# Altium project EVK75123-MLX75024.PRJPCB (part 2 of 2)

## Sheet Interfaces.SchDoc: Interfaces / PLL / Temp. Sensors
size A3; CheckedBy: ROB; Author: Vorname Nachname; DrawnBy: DST; Organization: BECOM BLUETECHNIX; Address1: Gutheil-Schoder-Gasse 17; Address2: A - 1230 Wien; Address3: AUSTRIA; DocumentNumber: 2; Revision: V1.0; SheetNumber: 2; SheetTotal: 4
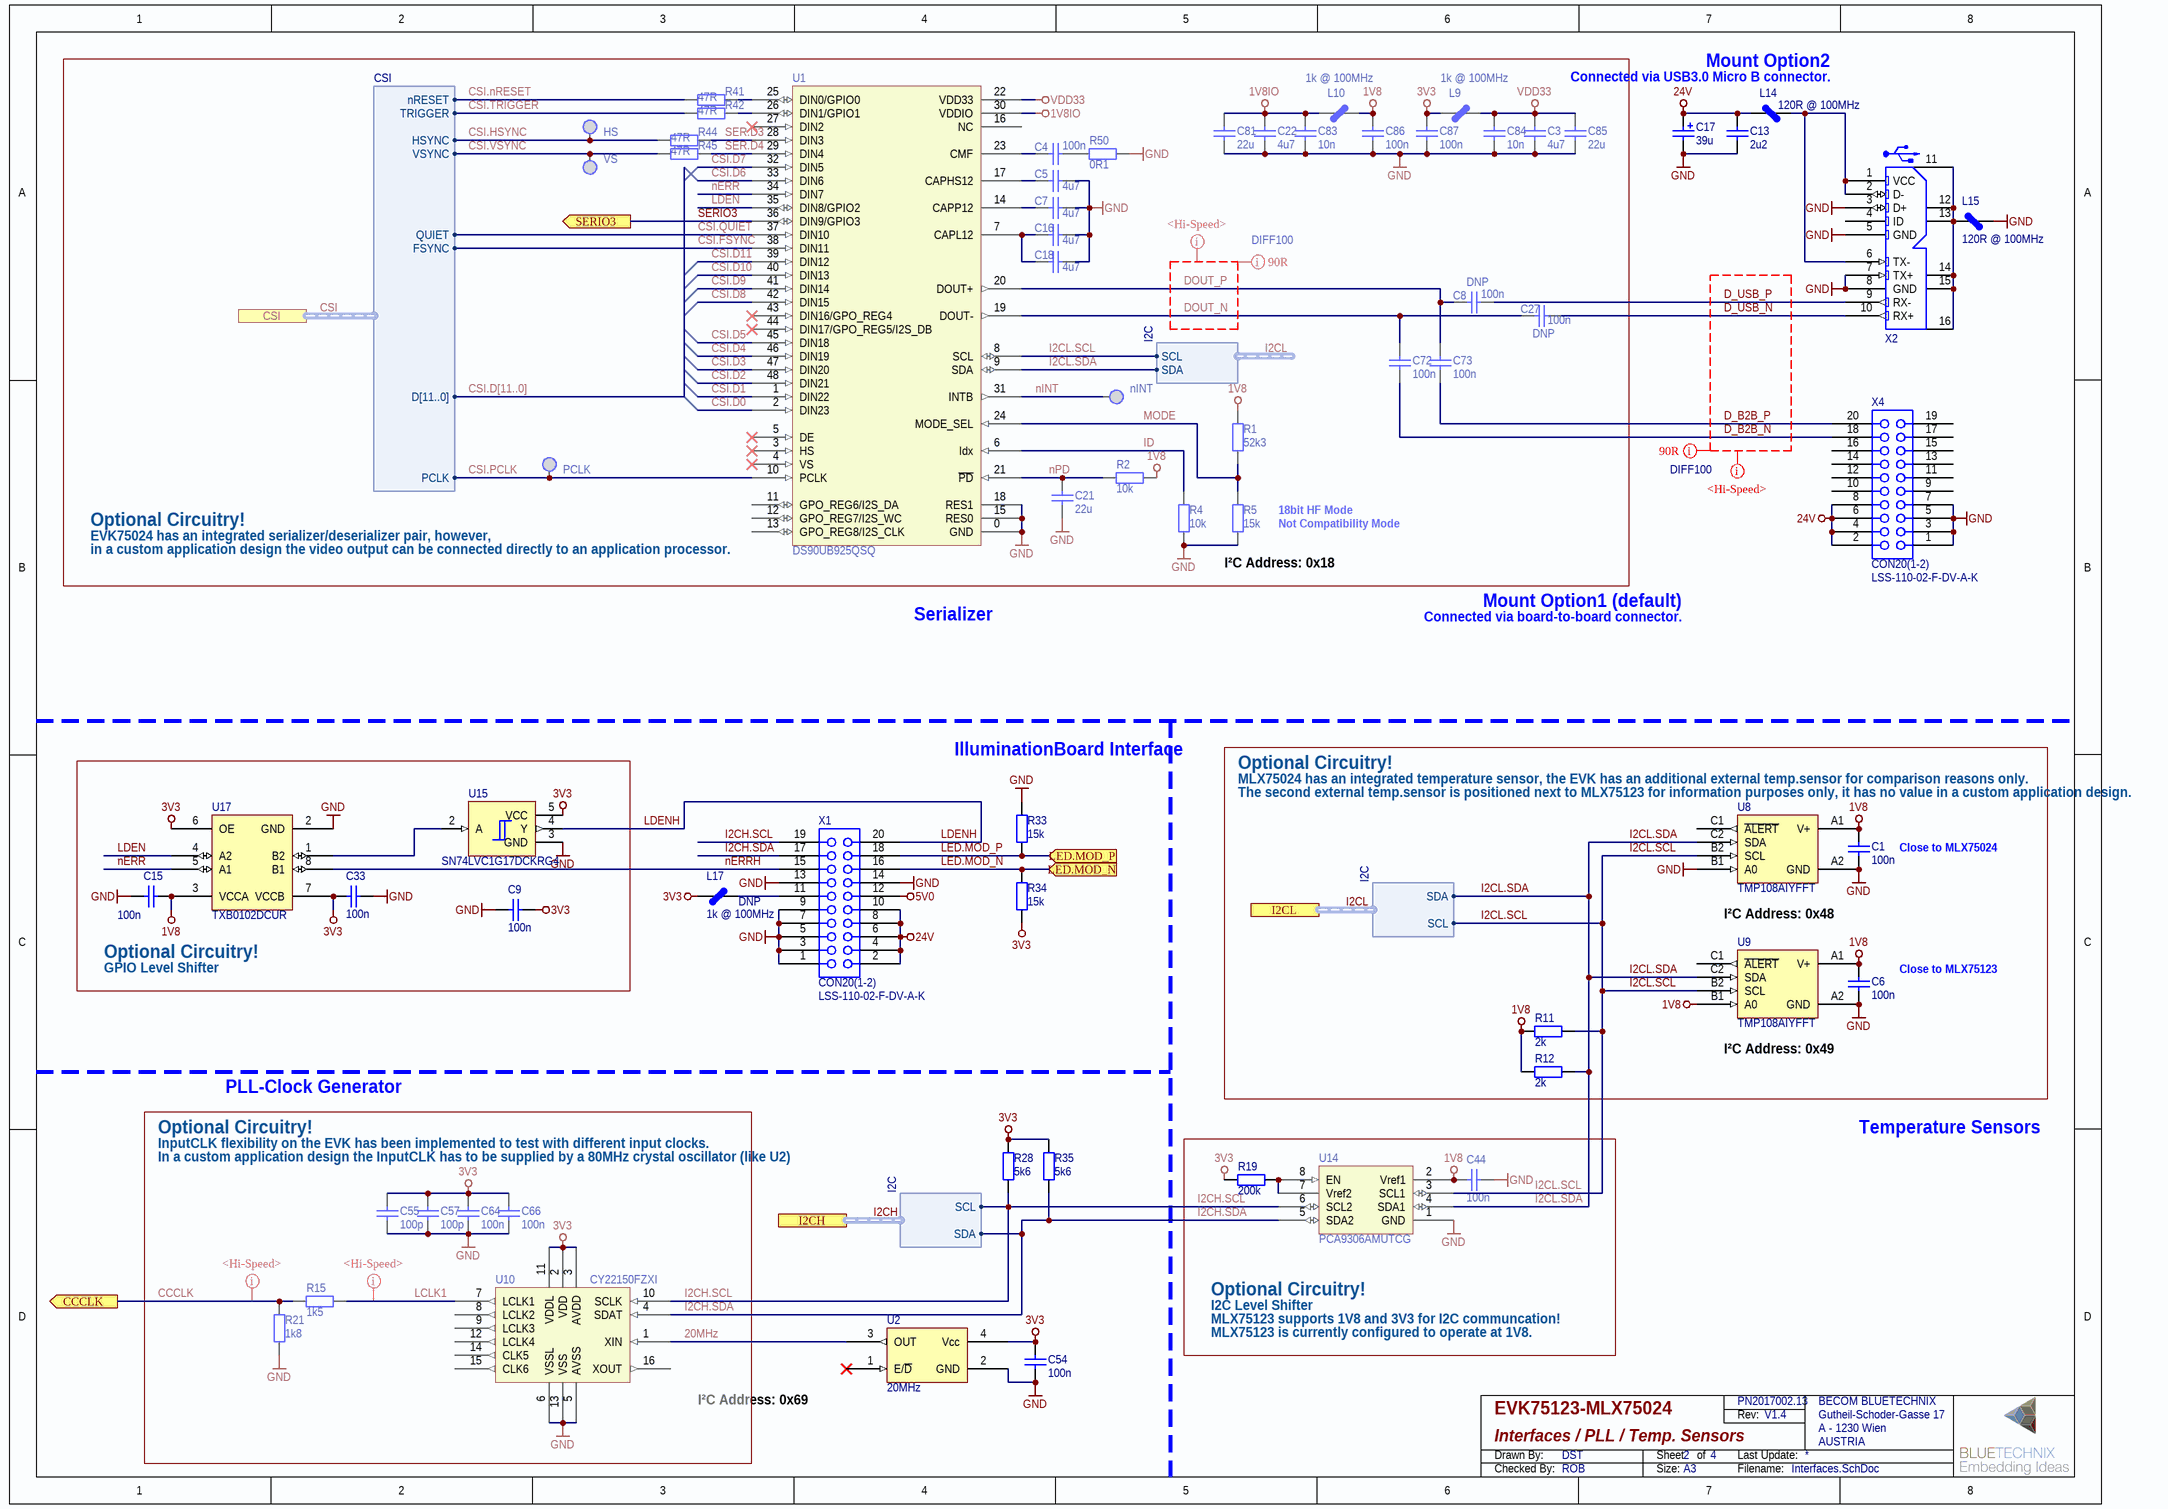
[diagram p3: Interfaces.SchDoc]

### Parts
C1  C: 100n  [0402]  (hidden comment: Capacitor non-polarized)
C3  C: 4u7  [0603]  (hidden comment: Capacitor non-polarized)
C4  C: 100n  [0402]  (hidden comment: Capacitor non-polarized)
C5  C: 4u7  [0603]  (hidden comment: Capacitor non-polarized)
C6  C: 100n  [0402]  (hidden comment: Capacitor non-polarized)
C7  C: 4u7  [0603]  (hidden comment: Capacitor non-polarized)
C8  C: 100n  MountOption: DNP  [0805]  (hidden comment: Capacitor non-polarized)
C9  C: 100n  [0402]  (hidden comment: Capacitor non-polarized)
C13  C: 2u2  [1210]  (hidden comment: Capacitor non-polarized)
C15  C: 100n  [0402]  (hidden comment: Capacitor non-polarized)
C16  C: 4u7  [0603]  (hidden comment: Capacitor non-polarized)
C17  C: 39u  [ELKO_SMD-8x7]  (hidden comment: Polarized Capicator)
C18  C: 4u7  [0603]  (hidden comment: Capacitor non-polarized)
C21  C: 22u  [0805]  (hidden comment: Capacitor non-polarized)
C22  C: 4u7  [0603]  (hidden comment: Capacitor non-polarized)
C27  C: 100n  MountOption: DNP  [0805]  (hidden comment: Capacitor non-polarized)
C33  C: 100n  [0402]  (hidden comment: Capacitor non-polarized)
C44  C: 100n  [0402]  (hidden comment: Capacitor non-polarized)
C54  C: 100n  [0402]  (hidden comment: Capacitor non-polarized)
C55  C: 100p  [0402]  (hidden comment: Capacitor non-polarized)
C57  C: 100p  [0402]  (hidden comment: Capacitor non-polarized)
C64  C: 100n  [0402]  (hidden comment: Capacitor non-polarized)
C66  C: 100n  [0402]  (hidden comment: Capacitor non-polarized)
C72  C: 100n  [0805]  (hidden comment: Capacitor non-polarized)
C73  C: 100n  [0805]  (hidden comment: Capacitor non-polarized)
C81  C: 22u  [0805]  (hidden comment: Capacitor non-polarized)
C83  C: 10n  [0603]  (hidden comment: Capacitor non-polarized)
C84  C: 10n  [0603]  (hidden comment: Capacitor non-polarized)
C85  C: 22u  [0805]  (hidden comment: Capacitor non-polarized)
C86  C: 100n  [0402]  (hidden comment: Capacitor non-polarized)
C87  C: 100n  [0402]  (hidden comment: Capacitor non-polarized)
HS  Test Pad  [PAD_1mm_SMD]  (value not drawn)  (no BOM)
L9  Z: 1k @ 100MHz  [0603]  (hidden comment: Ferrite)
L10  Z: 1k @ 100MHz  [0603]  (hidden comment: Ferrite)
L14  Z: 120R @ 100MHz  [0805]  (hidden comment: Ferrite)
L15  Z: 120R @ 100MHz  [0805]  (hidden comment: Ferrite)
L17  Z: 1k @ 100MHz  MountOption: DNP  [0603]  (hidden comment: Ferrite)
nINT  Test Pad  [PAD_1mm_SMD]  (value not drawn)  (no BOM)
PCLK  Test Pad  [PAD_1mm_SMD]  (value not drawn)  (no BOM)
R1  R: 52k3  [0402]  (hidden comment: Resistor)
R2  R: 10k  [0402]  (hidden comment: Resistor)
R4  R: 10k  [0402]  (hidden comment: Resistor)
R5  R: 15k  [0402]  (hidden comment: Resistor)
R11  R: 2k  [0402]  (hidden comment: Resistor)
R12  R: 2k  [0402]  (hidden comment: Resistor)
R15  R: 1k5  [0402]  (hidden comment: Resistor)
R19  R: 200k  [0402]  (hidden comment: Resistor)
R21  R: 1k8  [0402]  (hidden comment: Resistor)
R28  R: 5k6  [0402]  (hidden comment: Resistor)
R33  R: 15k  [0402]  (hidden comment: Resistor)
R34  R: 15k  [0402]  (hidden comment: Resistor)
R35  R: 5k6  [0402]  (hidden comment: Resistor)
R41  R: 47R  [0402]  (hidden comment: Resistor)
R42  R: 47R  [0402]  (hidden comment: Resistor)
R44  R: 47R  [0402]  (hidden comment: Resistor)
R45  R: 47R  [0402]  (hidden comment: Resistor)
R50  R: 0R1  [0402]  (hidden comment: Resistor)
U1  NAME: DS90UB925QSQ  [QFN48-0.5-7-largeEP]  (hidden comment: DS90UB925)
U2  Frequenz: 20MHz  [JO32]  (hidden comment: XTAL-IC)
U8  NAME: TMP108AIYFFT  [BGA6-0.4-0.25-1.2x0.8]  (hidden comment: TMP108)
U9  NAME: TMP108AIYFFT  [BGA6-0.4-0.25-1.2x0.8]  (hidden comment: TMP108)
U10  NAME: CY22150FZXI  [TSSOP16-0.65--6.4]  (hidden comment: PSoC Mixed Signal-Array)
U14  NAME: PCA9306AMUTCG  [VQFN8-0.5-1.6-0.6]  (hidden comment: PCA9306)
U15  NAME: SN74LVC1G17DCKRG4  [SOT353-0.65--2.6]  (hidden comment: SN74LVC1G17)
U17  NAME: TXB0102DCUR  [VSSOP8-0.5--3.2]  (hidden comment: TXB0102)
VS  Test Pad  [PAD_1mm_SMD]  (value not drawn)  (no BOM)
X1  CON20(1-2)  NAME: LSS-110-02-F-DV-A-K  [SAM-LSS-110-02-F-DV-A]
X2  USB_micro_3  [USB_micro_3]  (value not drawn)
X4  CON20(1-2)  NAME: LSS-110-02-F-DV-A-K  [SAM-LSS-110-02-F-DV-A]

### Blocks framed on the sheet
Optional Circuitry!: C3-C5 C7 C8 C16 C18 C21 C22 C27 C72 C73 C81 C83-C87 HS L9 L10 nINT PCLK R1 R2 R4 R5 R41 R42 R44 R45 R50 U1 VS
Optional Circuitry!: C9 C15 C33 U15 U17
Optional Circuitry!: C1 C6 R11 R12 U8 U9
Optional Circuitry!: C44 R19 U14

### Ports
CCCLK (out), CSI (harness CSI), I2CH (harness I2C), I2CL (harness I2C), LED.MOD_N (in), LED.MOD_P (in), SERIO3 (out)

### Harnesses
CSI: D[11..0], VSYNC, HSYNC, PCLK, QUIET, FSYNC, TRIGGER, nRESET
I2C: SCL, SDA

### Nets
1V8: C1.2 C6.2 C15.1 C44.2 C86.1 L10.2 R1.2 R2.2 R11.1 R12.1 U8.A1(V+) U9.A1(V+) U9.B1(A0) U14.2(Vref1) U17.3(VCCA)
1V8IO: C22.1 C81.2 C83.2 L10.1 U1.30(VDDIO)
3V3: C9.1 C33.2 C54.1 C55.2 C57.2 C64.2 C66.2 C87.1 L9.1 L17.1 R19.1 R28.2 R34.2 R35.2 U2.4(Vcc) U10.2(VDD) U10.3(AVDD) U10.11(VDDL) U15.5(VCC) U17.6(OE) U17.7(VCCB)
5V0: X1.12
24V: C13.2 C17.1 L14.1 X1.2 X1.4 X1.6 X1.8 X1.10 X4.2 X4.4 X4.6 X4.8
GND: C1.1 C3.2 C5.1 C6.1 C7.1 C9.2 C13.1 C15.2 C16.1 C17.2 C18.1 C21.1 C22.2 C33.1 C44.1 C54.2 C55.1 C57.1 C64.1 C66.1 C81.1 C83.1 C84.1 C85.1 C86.2 C87.2 L15.2 R4.1 R5.1 R21.1 R33.1 R50.1 U1.0(GND) U1.15(RES0) U1.18(RES1) U2.2(GND) U8.A2(GND) U8.B1(A0) U9.A2(GND) U10.5(AVSS) U10.6(VSSL) U10.13(VSS) U14.1(GND) U15.3(GND) U17.2(GND) X1.1 X1.3 X1.5 X1.7 X1.9 X1.13 X1.14 X2.3(D+) X2.5(GND) X2.7(TX+) X2.8(GND) X4.1 X4.3 X4.5 X4.7
VDD33: C3.1 C84.2 C85.2 L9.2 U1.22(VDD33)
20MHz: U2.3(OUT) U10.1(XIN)
CCCLK: R15.1 R21.2 ; port CCCLK
CSI.D0: U1.2(DIN23)
CSI.D1: U1.1(DIN22)
CSI.D2: U1.48(DIN21)
CSI.D3: U1.47(DIN20)
CSI.D4: U1.46(DIN19)
CSI.D5: U1.45(DIN18)
CSI.D6: U1.33(DIN6)
CSI.D7: U1.32(DIN5)
CSI.D8: U1.42(DIN15)
CSI.D9: U1.41(DIN14)
CSI.D10: U1.40(DIN13)
CSI.D11: U1.39(DIN12)
CSI.FSYNC: U1.38(DIN11) ; port CSI.FSYNC
CSI.HSYNC: HS.1 R44.1 ; port CSI.HSYNC
CSI.nRESET: R41.1 ; port CSI.nRESET
CSI.PCLK: PCLK.1 U1.10(PCLK) ; port CSI.PCLK
CSI.QUIET: U1.37(DIN10) ; port CSI.QUIET
CSI.TRIGGER: R42.1 ; port CSI.TRIGGER
CSI.VSYNC: R45.1 VS.1 ; port CSI.VSYNC
D_B2B_N: C72.1 X4.18
D_B2B_P: C73.1 X4.20
D_USB_N: C27.2 X2.10(RX+)
D_USB_P: C8.2 X2.9(RX-)
DOUT_N: C27.1 C72.2 U1.19(DOUT-)
DOUT_P: C8.1 C73.2 U1.20(DOUT+)
I2CH.SCL: R28.1 U10.10(SCLK) U14.6(SCL2) X1.19 ; port I2CH.SCL
I2CH.SDA: R35.1 U10.4(SDAT) U14.5(SDA2) X1.17 ; port I2CH.SDA
I2CL.SCL: R11.2 U1.8(SCL) U8.B2(SCL) U9.B2(SCL) U14.3(SCL1) ; port I2CL.SCL
I2CL.SDA: R12.2 U1.9(SDA) U8.C2(SDA) U9.C2(SDA) U14.4(SDA1) ; port I2CL.SDA
ID: R4.2 U1.6(Idx)
LCLK1: R15.2 U10.7(LCLK1)
LDEN: U1.35(DIN8/GPIO2) U17.4(A2)
LDENH: U15.4(Y) X1.20
LED.MOD_N: R34.1 X1.16 ; port LED.MOD_N
LED.MOD_P: R33.2 X1.18 ; port LED.MOD_P
MODE: R1.1 R5.2 U1.24(MODE_SEL)
nERR: U1.34(DIN7) U17.5(A1)
nERRH: U17.8(B1) X1.15
nINT: nINT.1 U1.31(INTB)
nPD: C21.2 R2.1 U1.21(~{PD})
SER.D3: R44.2 U1.28(DIN3)
SER.D4: R45.2 U1.29(DIN4)
SERIO3: U1.36(DIN9/GPIO3) ; port SERIO3
NetC4_1: C4.1 R50.2
NetC4_2: C4.2 U1.23(CMF)
NetC5_2: C5.2 U1.17(CAPHS12)
NetC7_2: C7.2 U1.14(CAPP12)
NetC16_2: C16.2 C18.2 U1.7(CAPL12)
NetL14_2: L14.2 X2.1(VCC) X2.2(D-) X2.6(TX-)
NetL15_1: L15.1 X2.11 X2.12 X2.13 X2.14 X2.15 X2.16
NetL17_2: L17.2 X1.11
NetR19_2: R19.2 U14.7(Vref2) U14.8(EN)
NetR41_2: R41.2 U1.25(DIN0/GPIO0)
NetR42_2: R42.2 U1.26(DIN1/GPIO1)
NetU15_2: U15.2(A) U17.1(B2)

Not connected (* = marked no-connect by the designer): U1 3(HS)* 4(VS)* 5(DE)* 11(GPO_REG6/I2S_DA) 12(GPO_REG7/I2S_WC) 13(GPO_REG8/I2S_CLK) 16(NC) 27(DIN2)* 43(DIN16/GPO_REG4)* 44(DIN17/GPO_REG5/I2S_DB)*; U2 1(E/~{D})*; U8 C1(~{ALERT}); U9 C1(~{ALERT}); U10 8(LCLK2) 9(LCLK3) 12(LCLK4) 14(CLK5) 15(CLK6) 16(XOUT); X2 4(ID); X4 9 10 11 12 13 14 15 16 17 19

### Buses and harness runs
bus CSI.D[11..0]
harness CSI = port CSI
harness I2CH = port I2CH
harness I2CL = port I2CL

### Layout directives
net class <Hi-Speed>: CCCLK, D_B2B_N, D_B2B_P, D_USB_N, D_USB_P, DOUT_N, DOUT_P, LCLK1
differential pair; net class DIFF100: D_B2B_N, D_B2B_P, D_USB_N, D_USB_P, DOUT_N, DOUT_P

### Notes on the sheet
- Mount Option2
- Connected via USB3.0 Micro B connector.
- (near R5) 18bit HF Mode
- EVK75024 has an integrated serializer/deserializer pair, however,
- (near U1) in a custom application design the video output can be connected directly to an application processor.
- (near R5) I²C Address: 0x18
- (near R5) Not Compatibility Mode
- Serializer
- Connected via board-to-board connector.
- (near X4) Mount Option1 (default)
- IlluminationBoard Interface
- MLX75024 has an integrated temperature sensor, the EVK has an additional external temp.sensor for comparison reasons only.
- The second external temp.sensor is positioned next to MLX75123 for information purposes only, it has no value in a custom application design.
- (near C1) Close to MLX75024
- I²C Address: 0x48
- GPIO Level Shifter
- (near C6) Close to MLX75123
- I²C Address: 0x49
- PLL-Clock Generator
- Optional Circuitry!
- In a custom application design the InputCLK has to be supplied by a 80MHz crystal oscillator (like U2)
- InputCLK flexibility on the EVK has been implemented to test with different input clocks.
- Temperature Sensors
- I2C Level Shifter
- MLX75123 supports 1V8 and 3V3 for I2C communcation!
- MLX75123 is currently configured to operate at 1V8.
- (near U10) I²C Address: 0x69

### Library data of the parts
C1 C4 C6 C15 C33 C44 C64 C66 C86 C87 = 54C877D5-E705-4C14-AD3D-8F4F7B57D597: C-0402-100n-16V-10%; Manufacturer: Murata; ArticleNumber: 710-0138; NAME: GRM155R71C104KA88D; Inventory Storage Name: LBaut; Inventory Storage Section: C3; Sachgruppe: C_KERAMIK; SachgruppeCode: Keramikscheiben; IsReviewed: 1; U: 16V; Toleranz: 10%; Dielektrikum: X7R; T_Koeffizient: ± 15%; T-bereich: -55°C : +125°C; Montage: SMD; InternalPrice: 0,009756; InternalStock: 539102
C3 C5 C7 C16 C18 C22 = E75EC942-B97D-4F35-9B30-0E69ABA45798: C-0603-4u7-6.3V-10%; Manufacturer: Kemet; ArticleNumber: 710-0008; NAME: C0603C475K9PAC; Inventory Storage Name: LBaut; Inventory Storage Section: CR1; Sachgruppe: C_KERAMIK; SachgruppeCode: Keramikscheiben; IsReviewed: 1; InternalPrice: 0,00975; InternalStock: 19132; U: 6.3V; Toleranz: 10%; Dielektrikum: X5R; T_Koeffizient: ± 15%; T-bereich: -55°C : +85°C; Montage: SMD
C8 C27 C72 C73 = 673ACA82-F2DF-4178-940F-1238A813E141: C-0805-100n-50V-10%; Manufacturer: AVX; ArticleNumber: 710-0012; NAME: 08055C104KAZ2A; Inventory Storage Name: LBaut; Inventory Storage Section: C1; Sachgruppe: C_KERAMIK; SachgruppeCode: Keramikscheiben; IsReviewed: 1; InternalPrice: 0,053478; InternalStock: 242; U: 50V; Toleranz: 10%; Dielektrikum: X7R; T_Koeffizient: ± 30ppm/°C; T-bereich: -55°C : +125°C; Montage: SMD
C9 C54 = 54C877D5-E705-4C14-AD3D-8F4F7B57D597: C-0402-100n-16V-10%; Manufacturer: Murata; ArticleNumber: 710-0138; NAME: GRM155R71C104KA88D; Inventory Storage Name: LBaut; Inventory Storage Section: C3; Sachgruppe: C_KERAMIK; SachgruppeCode: Keramikscheiben; IsReviewed: 1; Dielektrikum: X7R; Montage: SMD; T-bereich: -55°C : +125°C; T_Koeffizient: ± 15%; Toleranz: 10%; U: 16V; InternalPrice: 0,009756; InternalStock: 539102
C13 = c11633e3-883f-4ea1-bab5-305a930c1712: C-1210-2u2-100V-X7R; Manufacturer: Kemet; ArticleNumber: 710-0311; NAME: C1210C225K1RACTU; Inventory Storage Name: LBaut; Inventory Storage Section: C6; Sachgruppe: C_KERAMIK; SachgruppeCode: Keramikscheiben; IsReviewed: 1; InternalPrice: 0,222241; InternalStock: 196; U: 100V; Toleranz: 10%; Dielektrikum: X7R; T_Koeffizient: ± 15%; T-bereich: -55°C : +125°C; Montage: SMD
C17 = 44276342-0de9-47a7-a7a6-11334c4a2d95: C-39u-35V-20%-30mR; Manufacturer: Panasonic; ArticleNumber: 710-0385; NAME: 35SVPF39M; Inventory Storage Name: LBaut; Sachgruppe: C_ALUMINIUM_ELKO; SachgruppeCode: Aluminium Elektrolyt; IsReviewed: 1; U: 35V; Toleranz: 20%; ESR: 30mR; Z: 30mR @ 100kHz; T-bereich: -55°C : +105°C; Lebensdauer: 5000h @ 105°C; Bauform: 8.3x8.3x6.9; Montage: SMD; Kommentar: Irip=2.8A; InternalPrice: 0,442083; InternalStock: 68; Inventory Storage Section: C7
C21 C81 C85 = 9F754684-D939-469A-B40A-D1B375B83304: C-0805-22u-6.3V-20%; Manufacturer: AVX; ArticleNumber: 710-0282; NAME: 08056D226MAT2A; Inventory Storage Name: LBaut; Inventory Storage Section: C6; Sachgruppe: C_KERAMIK; SachgruppeCode: Keramikscheiben; IsReviewed: 1; InternalPrice: 0,139296; InternalStock: 574; U: 6.3V; Toleranz: 20%; Dielektrikum: X5R; T_Koeffizient: ±15%; T-bereich: -55°C :+125°C; Montage: SMD
C55 C57 = ec10d741-eb09-41f2-b621-026af504b23c: C-0402-100p-50V-5%; Manufacturer: Samsung; ArticleNumber: 710-0302; NAME: CL05C101JB5NNNC; Inventory Storage Name: LBaut; Sachgruppe: C_KERAMIK; SachgruppeCode: Keramikscheiben; IsReviewed: 1; InternalPrice: 0,006666; InternalStock: 8674; U: 50V; Toleranz: 5%; Dielektrikum: C0G; T-bereich: -55°C : +125°C; Montage: SMD; Inventory Storage Section: C6
C83 C84 = 7C0C21CA-74A8-454E-BED5-E74A03E0EDB6: C-0603-10n-25V-5%; Manufacturer: Kemet; ArticleNumber: 710-0271; NAME: C0603C103J3GACTU; Inventory Storage Name: LBaut; Inventory Storage Section: C6; Sachgruppe: C_KERAMIK; SachgruppeCode: Keramikscheiben; IsReviewed: 1; InternalPrice: 0,174117; InternalStock: 264; U: 25V; Toleranz: 5%; Dielektrikum: C0G; T_Koeffizient: ± 30ppm/°C; T-bereich: -55°C : +125°C; Montage: SMD
HS nINT PCLK VS = D58E77CC-74E0-4972-9B60-0D1F1EE06ED8: Test Pad 1mm; Manufacturer: Bluetechnix; ArticleNumber: 810-0021; Inventory Storage Name: L2; Sachgruppe: SV_TEST; IsReviewed: 1; Montage: THD
L9 L10 = EB1B1D42-458D-46E7-BD46-C9CB50225E79: F-0603-1000Z-500mA; Manufacturer: Taiyo Yuden; ArticleNumber: 770-0092; NAME: FBMH1608HM102-T; Inventory Storage Name: LBaut; Inventory Storage Section: I7; Sachgruppe: FI_FERRITPERLEN; SachgruppeCode: Ferritperlen; IsReviewed: 1; InternalPrice: 0,108507; InternalStock: 382; R_dc: 0R45; Frequenz: 900MHz; I_max: 0.5A; Montage: SMD; T-bereich: -40°C : +125°C
L14 L15 = 4558f3ef-a2ca-4732-a97e-33e36c5aad12: F-0805-120Z-5A; Manufacturer: MEC MARCOM; ArticleNumber: 740-0008; NAME: MFB-201209-0120PU; Inventory Storage Name: LBaut; Inventory Storage Section: L2; Sachgruppe: FI_FERRITPERLEN; SachgruppeCode: Ferritperlen; IsReviewed: 1; InternalPrice: 0,063082; InternalStock: 208; R_dc: 0R02; Bandbreite: 110R @ 1GHz; Frequenz: 300MHz; I_max: 5A; Montage: SMD; T-bereich: -55°C : +125°C
L17 = b9289626-3563-4556-94c6-b2bf7f242055: F-0603-1000Z-100mA; Manufacturer: Murata; ArticleNumber: 740-0011; NAME: BLM18BD102SN1D; Inventory Storage Name: LBaut; Inventory Storage Section: L2; Sachgruppe: FI_FERRITPERLEN; SachgruppeCode: Ferritperlen; IsReviewed: 1; InternalPrice: 0,018958; InternalStock: 710; R_dc: 0R85; Frequenz: 200MHz; I_max: 100mA; Montage: SMD; T-bereich: -55°C : +125°C
R1 = 07979F3D-4677-465C-93AF-4C0DB5A9740C: R-0402-52k3-1%; Manufacturer: Multicomp; ArticleNumber: 780-0113; NAME: MC 0.0625W 0402 1% 52K3; Inventory Storage Name: LBaut; Inventory Storage Section: R3; Sachgruppe: R_DICKSCHICHT; SachgruppeCode: Dickschicht; IsReviewed: 1; InternalPrice: 0,022692; InternalStock: 1828; P: 0.0625W; Toleranz: 1%; T_Koeffizient: ± 100ppm/°C; Montage: SMD; T-bereich: -55°C : +155°C
R2 R4 = BCCEBF77-39D2-4523-BB97-913D11062098: R-0402-10k-1%; manufacturer: YAGEO; ArticleNumber: 780-0217; Inventory Storage Name: LBaut; Inventory Storage Section: R5; NAME: RC0402FR-0710KL; Sachgruppe: R_DICKSCHICHT; SachgruppeCode: Dickschicht; Montage: SMD; P: 0.063W; T_Koeffizient: ± 250ppm/°C; Toleranz: 1%; IsReviewed: 1; T-bereich: -55°C : +155°C; InternalPrice: 0,028158; InternalStock: 1616
R5 = 5AE00D73-A272-4484-A2BE-57AC9ABCA7A7: R-0402-15k-1%; Manufacturer: YAGEO; ArticleNumber: 780-0130; NAME: RC0402FR-0715K0L; Inventory Storage Name: LBaut; Inventory Storage Section: R3; Sachgruppe: R_DICKSCHICHT; SachgruppeCode: Dickschicht; IsReviewed: 1; P: 0.063W; Toleranz: 1%; T_Koeffizient: ± 250ppm/°C; Montage: SMD; T-bereich: -55°C : +155°C; InternalPrice: 0,036444; InternalStock: 788
R11 R12 = BC2B87D0-B6C1-44F9-904C-ACAF31BEC71E: R-0402-2k-1%; Manufacturer: MULTICOMP; ArticleNumber: 780-0436; NAME: MC 0.0625W 0402 1% 2K; Inventory Storage Name: LBaut; Inventory Storage Section: R9; Sachgruppe: R_DICKSCHICHT; SachgruppeCode: Dickschicht; IsReviewed: 1; InternalPrice: 0,035294; InternalStock: 30; P: 0.063W; Toleranz: 1%; T_Koeffizient: ± 100ppm/°C; Montage: SMD; T-bereich: -55°C : +155°C
R15 = 9730678D-3891-499B-9B01-A89CC85559C4: R-0402-1k5-1%; Manufacturer: YAGEO; ArticleNumber: 780-0257; NAME: RC0402FR-071K5L; Inventory Storage Name: LBaut; Inventory Storage Section: R6; Sachgruppe: R_DICKSCHICHT; SachgruppeCode: Dickschicht; IsReviewed: 1; InternalPrice: 0,035634; InternalStock: 490; P: 0.063W; Toleranz: 1%; T_Koeffizient: ± 250ppm/°C; Montage: SMD; T-bereich: -55°C : +155°C
R19 = EB4C6C81-BAA5-401A-97FC-7C0F95811618: R-0402-200k-1%; Manufacturer: YAGEO; ArticleNumber: 780-0184; NAME: RC0402FR-07200KL; Inventory Storage Name: LBaut; Inventory Storage Section: R4; Sachgruppe: R_DICKSCHICHT; SachgruppeCode: Dickschicht; IsReviewed: 1; InternalPrice: 0,009047; InternalStock: 1480; P: 0.063W; Toleranz: 1%; T_Koeffizient: ± 100ppm/°C; Montage: SMD; T-bereich: -55°C : +155°C
R21 = 1021EC43-D7C6-4E9F-B4E5-559CA0DA3C67: R-0402-1k8-1%; Manufacturer: YAGEO; ArticleNumber: 780-0124; NAME: RC0402FR-071K8L; Inventory Storage Name: LBaut; Inventory Storage Section: R3; Sachgruppe: R_DICKSCHICHT; SachgruppeCode: Dickschicht; IsReviewed: 1; InternalPrice: 0,005937; InternalStock: 402; P: 0.063W; Toleranz: 1%; T_Koeffizient: ± 250ppm/°C; Montage: SMD
R28 R35 = 83EC2591-E07F-42F5-A99F-8FBBFCE4BDFC: R-0402-5k6-5%; Manufacturer: YAGEO; ArticleNumber: 780-0215; NAME: RC0402JR-075K6L; Inventory Storage Name: LBaut; Inventory Storage Section: R5; Sachgruppe: R_DICKSCHICHT; SachgruppeCode: Dickschicht; IsReviewed: 1; InternalPrice: 0,00795; InternalStock: 952; P: 0.063W; Toleranz: 5%; T_Koeffizient: ± 200ppm/°C; Montage: SMD; T-bereich: -55°C : +150°C
R33 R34 = 5AE00D73-A272-4484-A2BE-57AC9ABCA7A7: R-0402-15k-1%; Manufacturer: YAGEO; ArticleNumber: 780-0130; NAME: RC0402FR-0715K0L; Inventory Storage Name: LBaut; Inventory Storage Section: R3; Sachgruppe: R_DICKSCHICHT; SachgruppeCode: Dickschicht; IsReviewed: 1; InternalPrice: 0,036444; InternalStock: 788; P: 0.063W; Toleranz: 1%; T_Koeffizient: ± 250ppm/°C; Montage: SMD; T-bereich: -55°C : +155°C
R41 R42 R44 R45 = B17B00F1-DBD0-472B-A8A9-768E0D7D14BD: R-0402-47R-5%; Manufacturer: YAEGO; ArticleNumber: 780-0173; NAME: RC0402JR-0747RL; Inventory Storage Name: LBaut; Inventory Storage Section: R4; Sachgruppe: R_DICKSCHICHT; SachgruppeCode: Dickschicht; IsReviewed: 1; P: 0.063W; Toleranz: 5%; T_Koeffizient: ± 200ppm/°C; Montage: SMD; T-bereich: -55°C : +155°C; InternalPrice: 0,023346; InternalStock: 978
R50 = 366df4e7-ff92-4215-b9a2-968f2cab22c9: R-0402-0R1-1%; Manufacturer: PhyComp; ArticleNumber: 780-0603; NAME: RL0402FR-070R1L; Inventory Storage Name: LBaut; Sachgruppe: R_DICKSCHICHT; SachgruppeCode: Dickschicht; IsReviewed: 1; P: 0.063W; Toleranz: 1%; T_Koeffizient: ± 100ppm/°C; Montage: SMD; InternalPrice: 0,0875; InternalStock: 188; Inventory Storage Section: R11
U1 = 1691325b-6bd3-4e9e-84e0-1aaa7d8a455c: DS90UB925Q-Q1 5 to 85 MHz 24-Bit Color FPD-Link III Serializer; Manufacturer: TI; ArticleNumber: 700-1102; Inventory Storage Name: LBaut; Sachgruppe: IC_TREIBER_INTERFACE; SachgruppeCode: Treiber & Interface; IsReviewed: 1; Typ: 24 Bit LVDS Deserializer; Wege: 18/24 : 2; Interface: LVDS; T-bereich: -40°C : +105°C; Bauform: QFN48; Montage: SMD; U: VDD 1.8V, VIO 1.8V : 3.3V; InternalPrice: 8,505555; InternalStock: 10; Inventory Storage Section: U48
U2 = 00cff2d6-5d29-4f0c-95fc-66dce918587e: OSC-JO32-20MHz; Manufacturer: Microchip; ArticleNumber: 760-0134; NAME: DSC1001CL1-020.0000; Inventory Storage Name: LBaut; Sachgruppe: QO_OSZILLATOR; SachgruppeCode: Oszillatoren; IsReviewed: 1; Toleranz: ±50ppm; U: 1.8V : 3.3V; T-bereich: -40°C : +105°C; Bauform: 3.2x2.5; Montage: SMD; InternalPrice: 1,112307; InternalStock: 16; Inventory Storage Section: Y9
U8 U9 = 1756c951-2cf8-4c64-a988-e546f59afa21: ±1°C Accurate 12bit Digital Temperature Sensor; Manufacturer: Texas Instruments; ArticleNumber: 730-0256; Inventory Storage Name: LBaut; Inventory Storage Section: V19; Sachgruppe: SENSOREN; IsReviewed: 1; Interface: SMBus/I2C; Messbereich: -40°C : +125°C; U: 1.4V : 3.6V; Bauform: WCSP6 (DSBGA-6); Montage: SMD; Kommentar: I²C: 0x48 - 0x4B; PM: T8; InternalPrice: 1,331034; InternalStock: 118
U10 = ab1d2fae-9ac6-4ea7-8deb-ee514b9f58bf: Serial programmable clock generator; Manufacturer: Cypress; ArticleNumber: 700-0950; Inventory Storage Name: LBaut; Sachgruppe: IC_SPEZIAL; SachgruppeCode: Spezial Funktionen; IsReviewed: 1; InternalPrice: 3,498906; InternalStock: 12; Typ: Re-Programmable PLL; U: 2.375V : 3.465V; T-bereich: -40°C : +85°C; Bauform: TSSOP16; Montage: SMD; Kommentar: fo = 80kHz : 200MHz; Inventory Storage Section: U39
U14 = c6ef2881-e2fc-40f5-a959-5641457b75ea: DUAL BIDIRECTIONAL I2C BUS AND SMBus VOLTAGE-LEVEL TRANSLATOR; Manufacturer: ON Semiconductor; ArticleNumber: 700-1134; Inventory Storage Name: L2; Sachgruppe: IC_TREIBER_INTERFACE; SachgruppeCode: Treiber & Interface; IsReviewed: 1; InternalPrice: 0,411111; InternalStock: 2; Interface: I²C; T-bereich: -55°C : 125°C; Bauform: UQFN8; Montage: SMD; Kommentar: Vref1 < Vref2; topmark: AQ _; U: 1.2V : 3.3V, 1.8V : 5.5V
U15 = FD5746C1-CD80-4158-946D-D65AE2EC754E: 74LVC1G17; Manufacturer: Texas Instruments; ArticleNumber: 700-0571; Inventory Storage Name: LBaut; Inventory Storage Section: U18; Sachgruppe: IC_LOGIC; SachgruppeCode: Logic; IsReviewed: 1; InternalPrice: 0,132142; InternalStock: 2538; Logik-Gruppe (NOR): Schmitttrigger; Logik-Typ (7402): 7417; Serie (HCT): LVC; Trigger: state; Out-Typ: TTL; t_t: 4.4ns; U: 1.65V : 5.5V; T-bereich: -40°C : +85°C; Bauform: SOT353-5; Montage: SMD; topmark: C7_
U17 = 10037a6d-1755-4ddc-8842-5c10ed512f06: Dual Bidirectional Voltage level translator; Manufacturer: Texas Instruments; ArticleNumber: 700-1001; Inventory Storage Name: LBaut; Inventory Storage Section: U44; Sachgruppe: IC_TREIBER_INTERFACE; SachgruppeCode: Treiber & Interface; IsReviewed: 1; InternalPrice: 0,704761; InternalStock: 10; Typ: 2Bit bidir Level Translator; Wege: 2; T-bereich: -40°C : 85°C; Bauform: VSSOP; Montage: SMD; Kommentar: datarate: 100Mbps @3.3V; topmark: NFD_; U: 1.2V : 3.3V, 1.65V : 5.5V
X1 X4 = 379f8e5c-a288-4eeb-8f71-ca0e0501eadd: High speed hermaphrodotoc strip; Manufacturer: Samtec; ArticleNumber: 810-0543; Inventory Storage Name: LBaut; Inventory Storage Section: Box8; Sachgruppe: SV_MEZZANIN; SachgruppeCode: Mezzanin; IsReviewed: 1; InternalPrice: 1,270042; InternalStock: 324; Typ: B2B; Pole: 20; Gender: h; Winkel: 180°; Reihen: 2; Pitch: 0.635mm; I_max: 1.7A; Montage: SMD; Kommentar: hermaphroditic 7.49mm; T-bereich: -55°C : +125°C
X2 = 1b5fc05e-92d5-48fd-8827-3329ad07d580: Micro USB 3.0 SMD horizontal; Manufacturer: Würth Electronic; ArticleNumber: 810-0515; NAME: 692 622 030 100; Inventory Storage Name: LBaut; Inventory Storage Section: X20; Sachgruppe: SV_DIGITAL_IO; SachgruppeCode: digital I/O; IsReviewed: 1; InternalPrice: 1,306829; InternalStock: 12; Pole: 10; Gender: f; Winkel: 90°; I_max: 1.8A; T-bereich: -20°C : +85°C

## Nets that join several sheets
1V8: Power (1V8.1 C26.2 R20.1 U16.1), ToF-Sensor (L1.2 L6.1 L7.1 L8.1), Interfaces (15 pins)
3V3: Power (11 pins), ToF-Sensor (13 pins), Interfaces (21 pins)
3V3A: Power (3V3A.1 C19.2 U12.5), ToF-Sensor (C30.2 C31.2 L12.2 U6.11)
5V0: Power (16 pins), Interfaces (X1.12)
24V: Power (C60.2 R32.2 U3.2), Interfaces (12 pins)
ABIAS: Power (C43.1 U13.1), ToF-Sensor (ABIAS.1 C56.2 R3.2)
GND: Power (41 pins), ToF-Sensor (60 pins), Interfaces (60 pins)
VMIX: Power (R49.1 VMIXH.1), ToF-Sensor (9 pins)
CCCLK: ToF-Sensor (U7.B13), Interfaces (R15.1 R21.2)
CSI.D0: ToF-Sensor (U7.A30), Interfaces (U1.2)
CSI.D1: ToF-Sensor (U7.B27), Interfaces (U1.1)
CSI.D2: ToF-Sensor (U7.A29), Interfaces (U1.48)
CSI.D3: ToF-Sensor (U7.B26), Interfaces (U1.47)
CSI.D4: ToF-Sensor (U7.A28), Interfaces (U1.46)
CSI.D5: ToF-Sensor (U7.B25), Interfaces (U1.45)
CSI.D6: ToF-Sensor (U7.A27), Interfaces (U1.33)
CSI.D7: ToF-Sensor (U7.B24), Interfaces (U1.32)
CSI.D8: ToF-Sensor (U7.A26), Interfaces (U1.42)
CSI.D9: ToF-Sensor (U7.B23), Interfaces (U1.41)
CSI.D10: ToF-Sensor (U7.A25), Interfaces (U1.40)
CSI.D11: ToF-Sensor (U7.B22), Interfaces (U1.39)
CSI.FSYNC: ToF-Sensor (FS.1 U7.A31), Interfaces (U1.38)
CSI.HSYNC: ToF-Sensor (U7.B29), Interfaces (HS.1 R44.1)
CSI.nRESET: ToF-Sensor (U7.A14), Interfaces (R41.1)
CSI.PCLK: ToF-Sensor (U7.B28), Interfaces (PCLK.1 U1.10)
CSI.QUIET: ToF-Sensor (U7.A15), Interfaces (U1.37)
CSI.TRIGGER: ToF-Sensor (U7.A13), Interfaces (R42.1)
CSI.VSYNC: ToF-Sensor (U7.A32), Interfaces (R45.1 VS.1)
I2CH.SCL: Power (U11.5), Interfaces (R28.1 U10.10 U14.6 X1.19)
I2CH.SDA: Power (U11.4), Interfaces (R35.1 U10.4 U14.5 X1.17)
I2CL.SCL: ToF-Sensor (U7.A12), Interfaces (5 pins)
I2CL.SDA: ToF-Sensor (U7.B11), Interfaces (5 pins)
LED.MOD_N: ToF-Sensor (U7.A34), Interfaces (R34.1 X1.16)
LED.MOD_P: ToF-Sensor (U7.B31), Interfaces (R33.2 X1.18)
SERIO3: ToF-Sensor (R8.2), Interfaces (U1.36)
